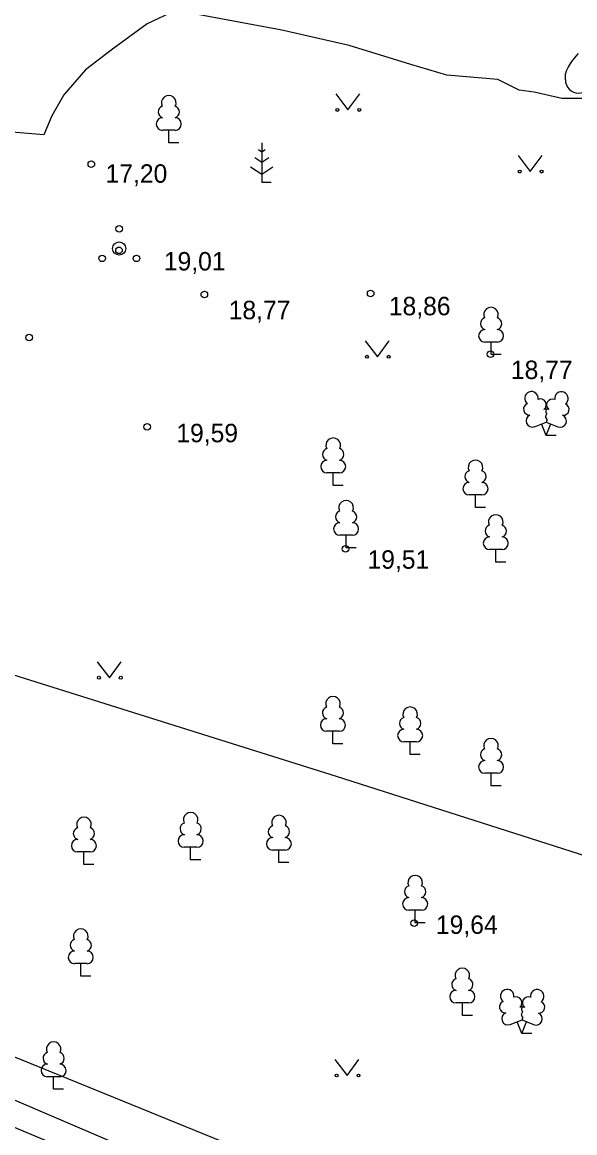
# Model space of a CAD drawing. Extents: x 713497 to 713863, y 6590062 to 6590327.
# Drawn here: x 713782.43 to 713803.4, y 6590236.16 to 6590278.31 of the extents above; entities that cross this region are included whole.
import ezdxf

# ---------------------------------------------------------------- set-up
doc = ezdxf.new("R2010")
doc.units = 0
for name, color, linetype in [('AED', 7, 'Continuous'), ('HALJASTUS', 7, 'Continuous'), ('KORGUS', 7, 'Continuous'), ('KPKAABEL', 7, 'Continuous'), ('MPKAABEL', 7, 'Continuous'), ('PUU', 7, 'Continuous'), ('SITRASS', 7, 'Continuous'), ('TEE', 7, 'Continuous')]:
    doc.layers.add(name, color=color, linetype=linetype)

msp = doc.modelspace()

# ---------------------------------------------------------------- linework, layer by layer
at = {"layer": 'AED'}
msp.add_lwpolyline([(713788.88, 6590285.23), (713788.26, 6590278.65), (713788.03, 6590278.65), (713787.17, 6590278.25), (713785.85, 6590277.29), (713784.83, 6590276.5), (713784.01, 6590275.55), (713783.55, 6590274.76), (713783.25, 6590274.03), (713776.26, 6590274.62), (713765.67, 6590275.3), (713754.93, 6590276.41), (713757.56, 6590281.99), (713749.75, 6590289.16), (713748.93, 6590295.3), (713750.19, 6590299.43)], dxfattribs=at)
at = {"layer": 'HALJASTUS'}
for p, q in [((713794.327, 6590275.587), (713794.79, 6590274.98)), ((713794.79, 6590274.98), (713795.236, 6590275.587)), ((713801.247, 6590273.247), (713801.71, 6590272.64)), ((713801.71, 6590272.64), (713802.156, 6590273.247)), ((713795.447, 6590266.217), (713795.91, 6590265.61)), ((713795.91, 6590265.61), (713796.356, 6590266.217)), ((713785.277, 6590254.037), (713785.74, 6590253.43)), ((713785.74, 6590253.43), (713786.186, 6590254.037)), ((713794.297, 6590238.937), (713794.76, 6590238.33)), ((713794.76, 6590238.33), (713795.206, 6590238.937))]:
    msp.add_line(p, q, dxfattribs=at)
msp.add_lwpolyline([(713835.82, 6590276.29), (713835.05, 6590276.56), (713830.82, 6590277.02), (713828.52, 6590277.18), (713826.1, 6590277.67), (713824.08, 6590277.83), (713822.14, 6590277.83), (713816.64, 6590278.64), (713814.22, 6590277.99), (713811.79, 6590277.2), (713807.92, 6590275.97), (713805.33, 6590275.41), (713802.91, 6590275.41), (713801.86, 6590275.65), (713801.29, 6590275.73), (713800.48, 6590276.13), (713798.54, 6590276.3), (713797.17, 6590276.7), (713794.83, 6590277.43), (713792.28, 6590278.01), (713788.27, 6590278.75)], dxfattribs=at)
for centre, radius in [((713794.389, 6590274.98), 0.055), ((713795.218, 6590274.98), 0.055), ((713801.309, 6590272.64), 0.055), ((713802.138, 6590272.64), 0.055), ((713786.11, 6590270.47), 0.125), ((713786.11, 6590269.72), 0.25), ((713785.46, 6590269.345), 0.125), ((713786.76, 6590269.345), 0.125), ((713782.69, 6590266.345), 0.125), ((713795.509, 6590265.61), 0.055), ((713796.338, 6590265.61), 0.055), ((713785.339, 6590253.43), 0.055), ((713786.168, 6590253.43), 0.055), ((713794.359, 6590238.33), 0.055), ((713795.188, 6590238.33), 0.055)]:
    msp.add_circle(centre, radius, dxfattribs=at)
at = {"layer": 'KORGUS'}
for centre in [(713785.05, 6590272.92), (713786.1, 6590269.65), (713789.34, 6590267.97), (713795.65, 6590268.01), (713800.2, 6590265.71), (713787.17, 6590262.95), (713794.7, 6590258.32), (713797.3, 6590244.11)]:
    msp.add_circle(centre, 0.125, dxfattribs=at)
at = {"layer": 'KPKAABEL'}
msp.add_lwpolyline([(713815.88, 6590242.79), (713794.35, 6590249.68), (713754.19, 6590262.29), (713731.48, 6590269.02), (713706.45, 6590275.72)], dxfattribs=at)
at = {"layer": 'MPKAABEL'}
msp.add_lwpolyline([(713802.35, 6590228.73), (713777.08, 6590239.56), (713776.78, 6590239.5)], dxfattribs=at)
at = {"layer": 'PUU'}
for p, q in [((713788.23, 6590274.205), (713787.75, 6590274.205)), ((713787.99, 6590273.73), (713787.99, 6590274.205)), ((713788.37, 6590273.73), (713787.99, 6590273.73)), ((713791.52, 6590273.73), (713791.52, 6590272.23)), ((713791.52, 6590273.38), (713791.396, 6590273.463)), ((713791.644, 6590273.463), (713791.52, 6590273.38)), ((713791.52, 6590272.98), (713791.253, 6590273.158)), ((713791.787, 6590273.158), (713791.52, 6590272.98)), ((713791.096, 6590272.819), (713791.52, 6590272.537)), ((713791.52, 6590272.537), (713791.944, 6590272.819)), ((713791.88, 6590272.23), (713791.52, 6590272.23)), ((713800.46, 6590266.165), (713799.98, 6590266.165)), ((713800.22, 6590265.69), (713800.22, 6590266.165)), ((713800.6, 6590265.69), (713800.22, 6590265.69)), ((713801.87, 6590262.955), (713802.315, 6590263.13)), ((713802.31, 6590262.62), (713802.135, 6590263.06)), ((713802.31, 6590262.62), (713802.49, 6590263.06)), ((713802.315, 6590263.13), (713802.755, 6590262.95)), ((713802.69, 6590262.62), (713802.31, 6590262.62)), ((713794.47, 6590261.205), (713793.99, 6590261.205)), ((713794.23, 6590260.73), (713794.23, 6590261.205)), ((713794.61, 6590260.73), (713794.23, 6590260.73)), ((713799.87, 6590260.365), (713799.39, 6590260.365)), ((713799.63, 6590259.89), (713799.63, 6590260.365)), ((713800.01, 6590259.89), (713799.63, 6590259.89)), ((713794.96, 6590258.835), (713794.48, 6590258.835)), ((713794.72, 6590258.36), (713794.72, 6590258.835)), ((713795.1, 6590258.36), (713794.72, 6590258.36)), ((713800.64, 6590258.295), (713800.16, 6590258.295)), ((713800.4, 6590257.82), (713800.4, 6590258.295)), ((713800.78, 6590257.82), (713800.4, 6590257.82)), ((713794.46, 6590251.395), (713793.98, 6590251.395)), ((713794.22, 6590250.92), (713794.22, 6590251.395)), ((713797.39, 6590250.995), (713796.91, 6590250.995)), ((713797.15, 6590250.52), (713797.15, 6590250.995)), ((713794.6, 6590250.92), (713794.22, 6590250.92)), ((713797.53, 6590250.52), (713797.15, 6590250.52)), ((713800.46, 6590249.805), (713799.98, 6590249.805)), ((713800.22, 6590249.33), (713800.22, 6590249.805)), ((713800.6, 6590249.33), (713800.22, 6590249.33)), ((713785.01, 6590246.815), (713784.53, 6590246.815)), ((713784.77, 6590246.34), (713784.77, 6590246.815)), ((713789.06, 6590246.995), (713788.58, 6590246.995)), ((713788.82, 6590246.52), (713788.82, 6590246.995)), ((713792.41, 6590246.885), (713791.93, 6590246.885)), ((713792.17, 6590246.41), (713792.17, 6590246.885)), ((713785.15, 6590246.34), (713784.77, 6590246.34)), ((713789.2, 6590246.52), (713788.82, 6590246.52)), ((713792.55, 6590246.41), (713792.17, 6590246.41)), ((713797.58, 6590244.605), (713797.1, 6590244.605)), ((713797.34, 6590244.13), (713797.34, 6590244.605)), ((713797.72, 6590244.13), (713797.34, 6590244.13)), ((713784.89, 6590242.575), (713784.41, 6590242.575)), ((713784.65, 6590242.1), (713784.65, 6590242.575)), ((713785.03, 6590242.1), (713784.65, 6590242.1)), ((713799.37, 6590241.085), (713798.89, 6590241.085)), ((713799.13, 6590240.61), (713799.13, 6590241.085)), ((713799.51, 6590240.61), (713799.13, 6590240.61)), ((713800.95, 6590240.265), (713801.395, 6590240.44)), ((713801.395, 6590240.44), (713801.835, 6590240.26)), ((713801.39, 6590239.93), (713801.215, 6590240.37)), ((713801.39, 6590239.93), (713801.57, 6590240.37)), ((713801.77, 6590239.93), (713801.39, 6590239.93)), ((713783.86, 6590238.285), (713783.38, 6590238.285)), ((713783.62, 6590237.81), (713783.62, 6590238.285)), ((713784, 6590237.81), (713783.62, 6590237.81))]:
    msp.add_line(p, q, dxfattribs=at)
for points in [[(713803.04, 6590276.12), (713803.04, 6590276.27), (713803.05, 6590276.335), (713803.085, 6590276.465), (713803.145, 6590276.585), (713803.29, 6590276.82), (713803.45, 6590277.025), (713803.54, 6590277.12)], [(713802.315, 6590263.625), (713802.295, 6590263.55), (713802.295, 6590263.53), (713802.305, 6590263.5), (713802.325, 6590263.465), (713802.33, 6590263.445), (713802.315, 6590263.41), (713802.29, 6590263.36), (713802.285, 6590263.335), (713802.29, 6590263.32), (713802.3, 6590263.29), (713802.335, 6590263.23), (713802.34, 6590263.21), (713802.335, 6590263.19), (713802.32, 6590263.155), (713802.315, 6590263.13)], [(713801.395, 6590240.935), (713801.375, 6590240.86), (713801.375, 6590240.84), (713801.385, 6590240.81), (713801.405, 6590240.775), (713801.41, 6590240.755), (713801.395, 6590240.72), (713801.37, 6590240.67), (713801.365, 6590240.645), (713801.37, 6590240.63), (713801.38, 6590240.6), (713801.415, 6590240.54), (713801.42, 6590240.52), (713801.415, 6590240.5), (713801.4, 6590240.465), (713801.395, 6590240.44)]]:
    msp.add_lwpolyline(points, dxfattribs=at)
for centre, radius, start, end in [((713803.54, 6590276.12), 0.5, 180, 0), ((713787.99, 6590275.25), 0.277, 332.5799, 207.4201), ((713787.82, 6590274.903), 0.233, 109.0217, 253.1415), ((713788.16, 6590274.903), 0.233, 286.8508, 70.9859), ((713787.753, 6590274.442), 0.238, 90.0016, 269.3953), ((713788.227, 6590274.442), 0.238, 270.6047, 89.9984), ((713800.22, 6590267.21), 0.277, 332.5799, 207.4201), ((713800.05, 6590266.863), 0.233, 109.0217, 253.1415), ((713800.39, 6590266.863), 0.233, 286.8508, 70.9859), ((713799.983, 6590266.402), 0.238, 90.0016, 269.3953), ((713800.457, 6590266.402), 0.238, 270.6047, 89.9984), ((713801.753, 6590264.034), 0.256, 111.5027, 232.5173), ((713801.753, 6590264.034), 0.256, 350.4856, 111.5002), ((713802.088, 6590263.784), 0.224, 308.5041, 111.5725), ((713802.551, 6590263.779), 0.225, 67.7016, 230.5126), ((713802.889, 6590264.025), 0.256, 67.6168, 188.6314), ((713802.889, 6590264.025), 0.256, 306.5997, 67.6143), ((713801.679, 6590263.623), 0.224, 111.4304, 274.4987), ((713802.314, 6590263.387), 0.237, 66.7655, 111.5015), ((713802.956, 6590263.613), 0.224, 264.6183, 67.6866), ((713801.784, 6590263.178), 0.237, 111.5014, 291.5004), ((713802.845, 6590263.17), 0.237, 247.6166, 67.6155), ((713794.23, 6590262.25), 0.277, 332.5799, 207.4201), ((713794.06, 6590261.903), 0.233, 109.0217, 253.1415), ((713794.4, 6590261.903), 0.233, 286.8508, 70.9859), ((713793.993, 6590261.442), 0.238, 90.0016, 269.3953), ((713794.467, 6590261.442), 0.238, 270.6047, 89.9984), ((713799.63, 6590261.41), 0.277, 332.5799, 207.4201), ((713799.46, 6590261.063), 0.233, 109.0217, 253.1415), ((713799.8, 6590261.063), 0.233, 286.8508, 70.9859), ((713799.393, 6590260.602), 0.238, 90.0016, 269.3953), ((713799.867, 6590260.602), 0.238, 270.6047, 89.9984), ((713794.72, 6590259.88), 0.277, 332.5799, 207.4201), ((713794.55, 6590259.533), 0.233, 109.0217, 253.1415), ((713794.89, 6590259.533), 0.233, 286.8508, 70.9859), ((713800.4, 6590259.34), 0.277, 332.5799, 207.4201), ((713794.483, 6590259.072), 0.238, 90.0016, 269.3953), ((713794.957, 6590259.072), 0.238, 270.6047, 89.9984), ((713800.23, 6590258.993), 0.233, 109.0217, 253.1415), ((713800.57, 6590258.993), 0.233, 286.8508, 70.9859), ((713800.163, 6590258.532), 0.238, 90.0016, 269.3953), ((713800.637, 6590258.532), 0.238, 270.6047, 89.9984), ((713794.22, 6590252.44), 0.277, 332.5799, 207.4201), ((713794.05, 6590252.093), 0.233, 109.0217, 253.1415), ((713794.39, 6590252.093), 0.233, 286.8508, 70.9859), ((713797.15, 6590252.04), 0.277, 332.5799, 207.4201), ((713793.983, 6590251.632), 0.238, 90.0016, 269.3953), ((713794.457, 6590251.632), 0.238, 270.6047, 89.9984), ((713796.98, 6590251.693), 0.233, 109.0217, 253.1415), ((713797.32, 6590251.693), 0.233, 286.8508, 70.9859), ((713796.913, 6590251.232), 0.238, 90.0016, 269.3953), ((713797.387, 6590251.232), 0.238, 270.6047, 89.9984), ((713800.22, 6590250.85), 0.277, 332.5799, 207.4201), ((713800.05, 6590250.503), 0.233, 109.0217, 253.1415), ((713800.39, 6590250.503), 0.233, 286.8508, 70.9859), ((713799.983, 6590250.042), 0.238, 90.0016, 269.3953), ((713800.457, 6590250.042), 0.238, 270.6047, 89.9984), ((713784.77, 6590247.86), 0.277, 332.5799, 207.4201), ((713788.82, 6590248.04), 0.277, 332.5799, 207.4201), ((713792.17, 6590247.93), 0.277, 332.5799, 207.4201), ((713784.6, 6590247.513), 0.233, 109.0217, 253.1415), ((713784.94, 6590247.513), 0.233, 286.8508, 70.9859), ((713788.65, 6590247.693), 0.233, 109.0217, 253.1415), ((713788.99, 6590247.693), 0.233, 286.8508, 70.9859), ((713792, 6590247.583), 0.233, 109.0217, 253.1415), ((713792.34, 6590247.583), 0.233, 286.8508, 70.9859), ((713784.533, 6590247.052), 0.238, 90.0016, 269.3953), ((713785.007, 6590247.052), 0.238, 270.6047, 89.9984), ((713788.583, 6590247.232), 0.238, 90.0016, 269.3953), ((713789.057, 6590247.232), 0.238, 270.6047, 89.9984), ((713791.933, 6590247.122), 0.238, 90.0016, 269.3953), ((713792.407, 6590247.122), 0.238, 270.6047, 89.9984), ((713797.34, 6590245.65), 0.277, 332.5799, 207.4201), ((713797.17, 6590245.303), 0.233, 109.0217, 253.1415), ((713797.51, 6590245.303), 0.233, 286.8508, 70.9859), ((713797.103, 6590244.842), 0.238, 90.0016, 269.3953), ((713797.577, 6590244.842), 0.238, 270.6047, 89.9984), ((713784.65, 6590243.62), 0.277, 332.5799, 207.4201), ((713784.48, 6590243.273), 0.233, 109.0217, 253.1415), ((713784.82, 6590243.273), 0.233, 286.8508, 70.9859), ((713784.413, 6590242.812), 0.238, 90.0016, 269.3953), ((713784.887, 6590242.812), 0.238, 270.6047, 89.9984), ((713799.13, 6590242.13), 0.277, 332.5799, 207.4201), ((713798.96, 6590241.783), 0.233, 109.0217, 253.1415), ((713799.3, 6590241.783), 0.233, 286.8508, 70.9859), ((713798.893, 6590241.322), 0.238, 90.0016, 269.3953), ((713799.367, 6590241.322), 0.238, 270.6047, 89.9984), ((713800.833, 6590241.344), 0.256, 111.5027, 232.5173), ((713800.833, 6590241.344), 0.256, 350.4856, 111.5002), ((713801.168, 6590241.094), 0.224, 308.5041, 111.5725), ((713801.631, 6590241.089), 0.225, 67.7016, 230.5126), ((713801.969, 6590241.335), 0.256, 67.6168, 188.6314), ((713801.969, 6590241.335), 0.256, 306.5997, 67.6143), ((713800.759, 6590240.933), 0.224, 111.4304, 274.4987), ((713801.394, 6590240.697), 0.237, 66.7655, 111.5015), ((713802.036, 6590240.923), 0.224, 264.6183, 67.6866), ((713800.864, 6590240.488), 0.237, 111.5014, 291.5004), ((713801.925, 6590240.48), 0.237, 247.6166, 67.6155), ((713783.62, 6590239.33), 0.277, 332.5799, 207.4201), ((713783.45, 6590238.983), 0.233, 109.0217, 253.1415), ((713783.79, 6590238.983), 0.233, 286.8508, 70.9859), ((713783.383, 6590238.522), 0.238, 90.0016, 269.3953), ((713783.857, 6590238.522), 0.238, 270.6047, 89.9984)]:
    msp.add_arc(centre, radius, start, end, dxfattribs=at)
at = {"layer": 'SITRASS'}
msp.add_lwpolyline([(713863.358, 6590205.976), (713841.44, 6590214.83), (713823.81, 6590222.07), (713798.2, 6590232.48), (713769.43, 6590244.2), (713757.31, 6590249.39), (713740.65, 6590256.05), (713706.71, 6590269.85)], dxfattribs=at)
at = {"layer": 'TEE'}
msp.add_lwpolyline([(713705.99, 6590269.548), (713709.56, 6590266.765), (713802.48, 6590227.84), (713863.358, 6590202.427)], dxfattribs=at)

# ---------------------------------------------------------------- texts
at = {"layer": 'KORGUS'}
for s, p in [('17,20', (713785.591, 6590272.215)), ('19,01', (713787.802, 6590268.885)), ('18,86', (713796.34, 6590267.185)), ('18,77', (713790.263, 6590267.035)), ('18,77', (713800.973, 6590264.765)), ('19,59', (713788.276, 6590262.365)), ('19,51', (713795.532, 6590257.565)), ('19,64', (713798.128, 6590243.705))]:
    msp.add_text(s, height=0.7, dxfattribs=at).set_placement(p)

doc.saveas('drawing.dxf')
